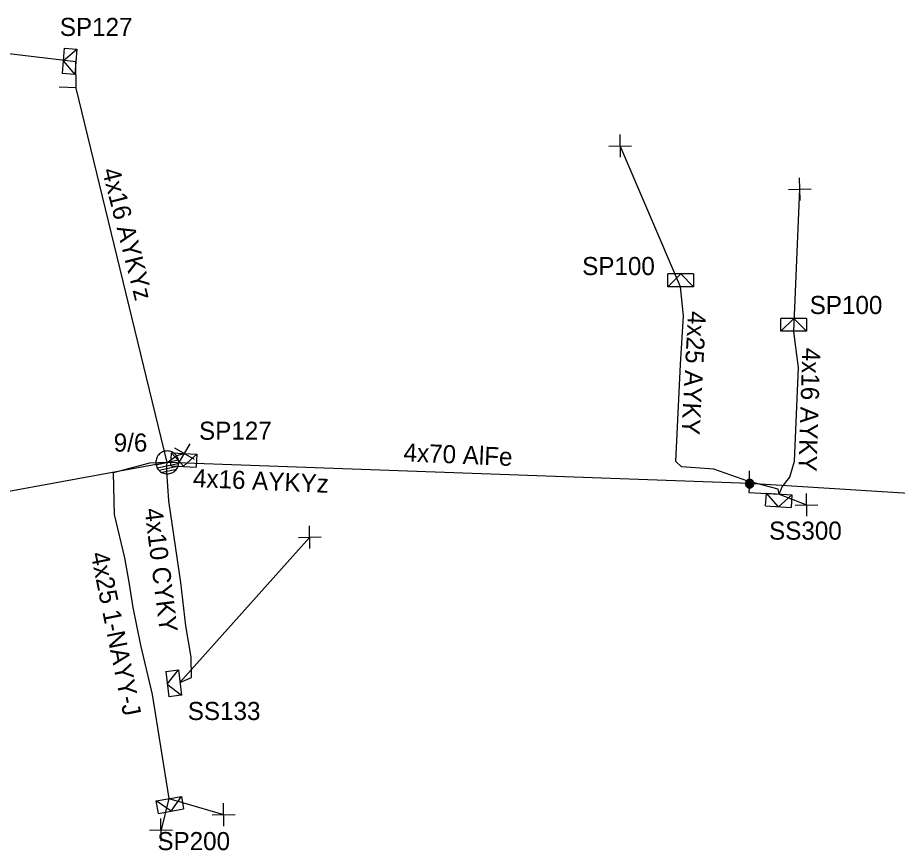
# Model space of a CAD drawing. Extents: x -762504 to -761250, y -1152974 to -1152253.
# Drawn here: x -761535.36 to -761487.02, y -1152548.71 to -1152502.95 of the extents above; entities that cross this region are included whole.
import ezdxf

# ---------------------------------------------------------------- set-up
doc = ezdxf.new("R2010")
doc.units = 0
for name, color, linetype in [('Vrstva 1', 7, 'Continuous'), ('Vrstva 12', 7, 'Continuous'), ('Vrstva 13', 7, 'Continuous'), ('Vrstva 2', 7, 'Continuous'), ('Vrstva 31', 7, 'Continuous'), ('Vrstva 33', 7, 'Continuous'), ('Vrstva 34', 7, 'Continuous'), ('Vrstva 5', 7, 'Continuous'), ('Vrstva 52', 7, 'Continuous'), ('Vrstva 54', 7, 'Continuous'), ('Vrstva 55', 7, 'Continuous'), ('Vrstva 59', 7, 'Continuous')]:
    doc.layers.add(name, color=color, linetype=linetype)

msp = doc.modelspace()

# ---------------------------------------------------------------- linework, layer by layer
at = {"layer": 'Vrstva 1'}
for points in [[(-761495.14, -1152528.56), (-761527.14, -1152527.39), (-761557.16, -1152532.89)], [(-761457.83, -1152530.5), (-761470.65, -1152530.09), (-761495.14, -1152528.56)]]:
    msp.add_lwpolyline(points, dxfattribs=at)
at = {"layer": 'Vrstva 13'}
for points in [[(-761532.142, -1152506.819), (-761533.078, -1152506.77)], [(-761526.523, -1152527.263), (-761526.54, -1152527.199), (-761526.563, -1152527.138), (-761526.593, -1152527.079), (-761526.629, -1152527.023), (-761526.67, -1152526.972), (-761526.717, -1152526.926), (-761526.768, -1152526.884), (-761526.823, -1152526.848), (-761526.882, -1152526.818), (-761526.944, -1152526.794), (-761527.008, -1152526.777), (-761527.073, -1152526.767), (-761527.139, -1152526.764), (-761527.204, -1152526.767), (-761527.27, -1152526.778), (-761527.333, -1152526.794), (-761527.395, -1152526.818), (-761527.454, -1152526.848), (-761527.509, -1152526.884), (-761527.56, -1152526.925), (-761527.607, -1152526.972), (-761527.648, -1152527.023), (-761527.684, -1152527.079), (-761527.714, -1152527.138), (-761527.738, -1152527.199), (-761527.755, -1152527.263), (-761527.765, -1152527.328), (-761527.769, -1152527.394), (-761527.765, -1152527.459), (-761527.755, -1152527.525), (-761527.738, -1152527.588), (-761527.714, -1152527.65), (-761527.684, -1152527.709), (-761527.648, -1152527.764), (-761527.607, -1152527.815), (-761527.56, -1152527.862), (-761527.509, -1152527.903), (-761527.454, -1152527.939), (-761527.395, -1152527.969), (-761527.333, -1152527.993), (-761527.269, -1152528.01), (-761527.205, -1152528.02), (-761527.139, -1152528.024), (-761527.073, -1152528.02), (-761527.008, -1152528.01), (-761526.944, -1152527.993), (-761526.882, -1152527.969), (-761526.824, -1152527.939), (-761526.768, -1152527.903), (-761526.717, -1152527.862), (-761526.67, -1152527.815), (-761526.629, -1152527.764), (-761526.593, -1152527.709), (-761526.563, -1152527.65), (-761526.539, -1152527.588), (-761526.522, -1152527.525), (-761526.512, -1152527.46), (-761526.509, -1152527.394), (-761526.512, -1152527.328), (-761526.523, -1152527.263)], [(-761527.757, -1152527.521), (-761526.525, -1152527.259)], [(-761527.692, -1152527.688), (-761526.546, -1152527.445)], [(-761527.574, -1152527.814), (-761526.583, -1152527.603)], [(-761527.409, -1152527.93), (-761526.696, -1152527.779)], [(-761495.14, -1152528.326), (-761495.14, -1152527.856)], [(-761494.905, -1152528.561), (-761494.906, -1152528.537), (-761494.91, -1152528.512), (-761494.916, -1152528.489), (-761494.925, -1152528.466), (-761494.936, -1152528.444), (-761494.949, -1152528.423), (-761494.965, -1152528.404), (-761494.982, -1152528.387), (-761495.001, -1152528.371), (-761495.022, -1152528.358), (-761495.044, -1152528.347), (-761495.067, -1152528.338), (-761495.091, -1152528.331), (-761495.115, -1152528.327), (-761495.14, -1152528.326), (-761495.164, -1152528.327), (-761495.188, -1152528.331), (-761495.212, -1152528.338), (-761495.235, -1152528.347), (-761495.257, -1152528.358), (-761495.278, -1152528.371), (-761495.297, -1152528.387), (-761495.314, -1152528.404), (-761495.33, -1152528.423), (-761495.343, -1152528.444), (-761495.354, -1152528.466), (-761495.363, -1152528.489), (-761495.369, -1152528.512), (-761495.373, -1152528.537), (-761495.375, -1152528.561), (-761495.373, -1152528.586), (-761495.369, -1152528.61), (-761495.363, -1152528.634), (-761495.354, -1152528.657), (-761495.343, -1152528.679), (-761495.33, -1152528.699), (-761495.314, -1152528.718), (-761495.297, -1152528.736), (-761495.278, -1152528.751), (-761495.257, -1152528.765), (-761495.235, -1152528.776), (-761495.212, -1152528.785), (-761495.188, -1152528.791), (-761495.164, -1152528.795), (-761495.14, -1152528.796), (-761495.115, -1152528.795), (-761495.091, -1152528.791), (-761495.067, -1152528.785), (-761495.044, -1152528.776), (-761495.022, -1152528.765), (-761495.001, -1152528.751), (-761494.982, -1152528.736), (-761494.965, -1152528.718), (-761494.949, -1152528.699), (-761494.936, -1152528.679), (-761494.925, -1152528.657), (-761494.916, -1152528.634), (-761494.91, -1152528.61), (-761494.906, -1152528.586), (-761494.905, -1152528.561)], [(-761494.905, -1152528.561), (-761494.906, -1152528.537), (-761494.91, -1152528.512), (-761494.916, -1152528.489), (-761494.925, -1152528.466), (-761494.936, -1152528.444), (-761494.949, -1152528.423), (-761494.965, -1152528.404), (-761494.982, -1152528.387), (-761495.001, -1152528.371), (-761495.022, -1152528.358), (-761495.044, -1152528.347), (-761495.067, -1152528.338), (-761495.091, -1152528.331), (-761495.115, -1152528.327), (-761495.14, -1152528.326), (-761495.164, -1152528.327), (-761495.188, -1152528.331), (-761495.212, -1152528.338), (-761495.235, -1152528.347), (-761495.257, -1152528.358), (-761495.278, -1152528.371), (-761495.297, -1152528.387), (-761495.314, -1152528.404), (-761495.33, -1152528.423), (-761495.343, -1152528.444), (-761495.354, -1152528.466), (-761495.363, -1152528.489), (-761495.369, -1152528.512), (-761495.373, -1152528.537), (-761495.375, -1152528.561), (-761495.373, -1152528.586), (-761495.369, -1152528.61), (-761495.363, -1152528.634), (-761495.354, -1152528.657), (-761495.343, -1152528.679), (-761495.33, -1152528.699), (-761495.314, -1152528.718), (-761495.297, -1152528.736), (-761495.278, -1152528.751), (-761495.257, -1152528.765), (-761495.235, -1152528.776), (-761495.212, -1152528.785), (-761495.188, -1152528.791), (-761495.164, -1152528.795), (-761495.14, -1152528.796), (-761495.115, -1152528.795), (-761495.091, -1152528.791), (-761495.067, -1152528.785), (-761495.044, -1152528.776), (-761495.022, -1152528.765), (-761495.001, -1152528.751), (-761494.982, -1152528.736), (-761494.965, -1152528.718), (-761494.949, -1152528.699), (-761494.936, -1152528.679), (-761494.925, -1152528.657), (-761494.916, -1152528.634), (-761494.91, -1152528.61), (-761494.906, -1152528.586), (-761494.905, -1152528.561)], [(-761494.934, -1152528.561), (-761494.935, -1152528.54), (-761494.939, -1152528.518), (-761494.944, -1152528.498), (-761494.952, -1152528.478), (-761494.962, -1152528.459), (-761494.973, -1152528.44), (-761494.987, -1152528.424), (-761495.002, -1152528.409), (-761495.019, -1152528.395), (-761495.037, -1152528.383), (-761495.056, -1152528.374), (-761495.076, -1152528.366), (-761495.097, -1152528.36), (-761495.118, -1152528.357), (-761495.14, -1152528.356), (-761495.161, -1152528.357), (-761495.182, -1152528.36), (-761495.203, -1152528.366), (-761495.223, -1152528.374), (-761495.242, -1152528.383), (-761495.26, -1152528.395), (-761495.277, -1152528.409), (-761495.292, -1152528.424), (-761495.306, -1152528.44), (-761495.317, -1152528.459), (-761495.327, -1152528.478), (-761495.335, -1152528.498), (-761495.34, -1152528.518), (-761495.344, -1152528.54), (-761495.345, -1152528.561), (-761495.344, -1152528.583), (-761495.34, -1152528.604), (-761495.335, -1152528.625), (-761495.327, -1152528.645), (-761495.317, -1152528.664), (-761495.306, -1152528.682), (-761495.292, -1152528.699), (-761495.277, -1152528.714), (-761495.26, -1152528.727), (-761495.242, -1152528.739), (-761495.223, -1152528.749), (-761495.203, -1152528.757), (-761495.182, -1152528.762), (-761495.161, -1152528.765), (-761495.14, -1152528.767), (-761495.118, -1152528.765), (-761495.097, -1152528.762), (-761495.076, -1152528.757), (-761495.056, -1152528.749), (-761495.037, -1152528.739), (-761495.019, -1152528.727), (-761495.002, -1152528.714), (-761494.987, -1152528.699), (-761494.973, -1152528.682), (-761494.962, -1152528.664), (-761494.952, -1152528.645), (-761494.944, -1152528.625), (-761494.939, -1152528.604), (-761494.935, -1152528.583), (-761494.934, -1152528.561)], [(-761494.964, -1152528.561), (-761494.965, -1152528.543), (-761494.968, -1152528.525), (-761494.972, -1152528.507), (-761494.979, -1152528.49), (-761494.987, -1152528.473), (-761494.997, -1152528.458), (-761495.009, -1152528.444), (-761495.022, -1152528.431), (-761495.036, -1152528.419), (-761495.052, -1152528.409), (-761495.068, -1152528.401), (-761495.085, -1152528.394), (-761495.103, -1152528.389), (-761495.121, -1152528.386), (-761495.14, -1152528.385), (-761495.158, -1152528.386), (-761495.176, -1152528.389), (-761495.194, -1152528.394), (-761495.211, -1152528.401), (-761495.227, -1152528.409), (-761495.243, -1152528.419), (-761495.257, -1152528.431), (-761495.27, -1152528.444), (-761495.282, -1152528.458), (-761495.292, -1152528.473), (-761495.3, -1152528.49), (-761495.307, -1152528.507), (-761495.312, -1152528.525), (-761495.314, -1152528.543), (-761495.315, -1152528.561), (-761495.314, -1152528.58), (-761495.312, -1152528.598), (-761495.307, -1152528.616), (-761495.3, -1152528.633), (-761495.292, -1152528.649), (-761495.282, -1152528.665), (-761495.27, -1152528.679), (-761495.257, -1152528.692), (-761495.243, -1152528.703), (-761495.227, -1152528.713), (-761495.211, -1152528.722), (-761495.194, -1152528.728), (-761495.176, -1152528.733), (-761495.158, -1152528.736), (-761495.14, -1152528.737), (-761495.121, -1152528.736), (-761495.103, -1152528.733), (-761495.085, -1152528.728), (-761495.068, -1152528.722), (-761495.052, -1152528.713), (-761495.036, -1152528.703), (-761495.022, -1152528.692), (-761495.009, -1152528.679), (-761494.997, -1152528.665), (-761494.987, -1152528.649), (-761494.979, -1152528.633), (-761494.972, -1152528.616), (-761494.968, -1152528.598), (-761494.965, -1152528.58), (-761494.964, -1152528.561)], [(-761494.993, -1152528.561), (-761494.994, -1152528.546), (-761494.997, -1152528.531), (-761495.001, -1152528.516), (-761495.006, -1152528.502), (-761495.013, -1152528.488), (-761495.021, -1152528.475), (-761495.031, -1152528.463), (-761495.042, -1152528.453), (-761495.054, -1152528.443), (-761495.067, -1152528.435), (-761495.08, -1152528.428), (-761495.094, -1152528.422), (-761495.109, -1152528.418), (-761495.124, -1152528.416), (-761495.14, -1152528.415), (-761495.155, -1152528.416), (-761495.17, -1152528.418), (-761495.185, -1152528.422), (-761495.199, -1152528.428), (-761495.213, -1152528.435), (-761495.226, -1152528.443), (-761495.237, -1152528.453), (-761495.248, -1152528.463), (-761495.258, -1152528.475), (-761495.266, -1152528.488), (-761495.273, -1152528.502), (-761495.279, -1152528.516), (-761495.283, -1152528.531), (-761495.285, -1152528.546), (-761495.286, -1152528.561), (-761495.285, -1152528.576), (-761495.283, -1152528.592), (-761495.279, -1152528.606), (-761495.273, -1152528.621), (-761495.266, -1152528.634), (-761495.258, -1152528.647), (-761495.248, -1152528.659), (-761495.237, -1152528.67), (-761495.226, -1152528.679), (-761495.213, -1152528.688), (-761495.199, -1152528.695), (-761495.185, -1152528.7), (-761495.17, -1152528.704), (-761495.155, -1152528.707), (-761495.14, -1152528.707), (-761495.124, -1152528.707), (-761495.109, -1152528.704), (-761495.094, -1152528.7), (-761495.08, -1152528.695), (-761495.067, -1152528.688), (-761495.054, -1152528.679), (-761495.042, -1152528.67), (-761495.031, -1152528.659), (-761495.021, -1152528.647), (-761495.013, -1152528.634), (-761495.006, -1152528.621), (-761495.001, -1152528.606), (-761494.997, -1152528.592), (-761494.994, -1152528.576), (-761494.993, -1152528.561)], [(-761495.023, -1152528.561), (-761495.024, -1152528.549), (-761495.026, -1152528.537), (-761495.029, -1152528.525), (-761495.033, -1152528.514), (-761495.039, -1152528.503), (-761495.045, -1152528.493), (-761495.053, -1152528.483), (-761495.062, -1152528.475), (-761495.071, -1152528.467), (-761495.081, -1152528.46), (-761495.092, -1152528.455), (-761495.104, -1152528.45), (-761495.115, -1152528.447), (-761495.127, -1152528.445), (-761495.14, -1152528.445), (-761495.152, -1152528.445), (-761495.164, -1152528.447), (-761495.176, -1152528.45), (-761495.187, -1152528.455), (-761495.198, -1152528.46), (-761495.208, -1152528.467), (-761495.218, -1152528.475), (-761495.226, -1152528.483), (-761495.234, -1152528.493), (-761495.241, -1152528.503), (-761495.246, -1152528.514), (-761495.25, -1152528.525), (-761495.254, -1152528.537), (-761495.256, -1152528.549), (-761495.256, -1152528.561), (-761495.256, -1152528.573), (-761495.254, -1152528.585), (-761495.25, -1152528.597), (-761495.246, -1152528.609), (-761495.241, -1152528.619), (-761495.234, -1152528.63), (-761495.226, -1152528.639), (-761495.218, -1152528.648), (-761495.208, -1152528.655), (-761495.198, -1152528.662), (-761495.187, -1152528.668), (-761495.176, -1152528.672), (-761495.164, -1152528.675), (-761495.152, -1152528.677), (-761495.14, -1152528.678), (-761495.127, -1152528.677), (-761495.115, -1152528.675), (-761495.104, -1152528.672), (-761495.092, -1152528.668), (-761495.081, -1152528.662), (-761495.071, -1152528.655), (-761495.062, -1152528.648), (-761495.053, -1152528.639), (-761495.045, -1152528.63), (-761495.039, -1152528.619), (-761495.033, -1152528.609), (-761495.029, -1152528.597), (-761495.026, -1152528.585), (-761495.024, -1152528.573), (-761495.023, -1152528.561)], [(-761495.053, -1152528.561), (-761495.053, -1152528.552), (-761495.055, -1152528.543), (-761495.057, -1152528.534), (-761495.06, -1152528.526), (-761495.064, -1152528.518), (-761495.069, -1152528.51), (-761495.075, -1152528.503), (-761495.081, -1152528.497), (-761495.089, -1152528.491), (-761495.096, -1152528.486), (-761495.104, -1152528.482), (-761495.113, -1152528.478), (-761495.121, -1152528.476), (-761495.131, -1152528.475), (-761495.14, -1152528.474), (-761495.149, -1152528.475), (-761495.158, -1152528.476), (-761495.166, -1152528.478), (-761495.175, -1152528.482), (-761495.183, -1152528.486), (-761495.191, -1152528.491), (-761495.198, -1152528.497), (-761495.204, -1152528.503), (-761495.21, -1152528.51), (-761495.215, -1152528.518), (-761495.219, -1152528.526), (-761495.222, -1152528.534), (-761495.225, -1152528.543), (-761495.226, -1152528.552), (-761495.227, -1152528.561), (-761495.226, -1152528.57), (-761495.225, -1152528.579), (-761495.222, -1152528.588), (-761495.219, -1152528.597), (-761495.215, -1152528.605), (-761495.21, -1152528.612), (-761495.204, -1152528.619), (-761495.198, -1152528.626), (-761495.191, -1152528.632), (-761495.183, -1152528.637), (-761495.175, -1152528.641), (-761495.166, -1152528.644), (-761495.158, -1152528.646), (-761495.149, -1152528.648), (-761495.14, -1152528.648), (-761495.131, -1152528.648), (-761495.121, -1152528.646), (-761495.113, -1152528.644), (-761495.104, -1152528.641), (-761495.096, -1152528.637), (-761495.088, -1152528.632), (-761495.081, -1152528.626), (-761495.075, -1152528.619), (-761495.069, -1152528.612), (-761495.064, -1152528.605), (-761495.06, -1152528.597), (-761495.057, -1152528.588), (-761495.055, -1152528.579), (-761495.053, -1152528.57), (-761495.053, -1152528.561)], [(-761495.082, -1152528.561), (-761495.083, -1152528.555), (-761495.084, -1152528.549), (-761495.085, -1152528.544), (-761495.087, -1152528.538), (-761495.09, -1152528.533), (-761495.093, -1152528.527), (-761495.097, -1152528.523), (-761495.101, -1152528.519), (-761495.106, -1152528.515), (-761495.111, -1152528.512), (-761495.116, -1152528.509), (-761495.122, -1152528.507), (-761495.128, -1152528.505), (-761495.134, -1152528.504), (-761495.14, -1152528.504), (-761495.146, -1152528.504), (-761495.152, -1152528.505), (-761495.157, -1152528.507), (-761495.163, -1152528.509), (-761495.168, -1152528.512), (-761495.173, -1152528.515), (-761495.178, -1152528.519), (-761495.182, -1152528.523), (-761495.186, -1152528.527), (-761495.189, -1152528.533), (-761495.192, -1152528.538), (-761495.194, -1152528.544), (-761495.196, -1152528.549), (-761495.197, -1152528.555), (-761495.197, -1152528.561), (-761495.197, -1152528.567), (-761495.196, -1152528.573), (-761495.194, -1152528.579), (-761495.192, -1152528.585), (-761495.189, -1152528.59), (-761495.186, -1152528.595), (-761495.182, -1152528.6), (-761495.178, -1152528.604), (-761495.173, -1152528.608), (-761495.168, -1152528.611), (-761495.163, -1152528.614), (-761495.157, -1152528.616), (-761495.152, -1152528.617), (-761495.146, -1152528.618), (-761495.14, -1152528.619), (-761495.134, -1152528.618), (-761495.128, -1152528.617), (-761495.122, -1152528.616), (-761495.116, -1152528.614), (-761495.111, -1152528.611), (-761495.106, -1152528.608), (-761495.101, -1152528.604), (-761495.097, -1152528.6), (-761495.093, -1152528.595), (-761495.09, -1152528.59), (-761495.087, -1152528.585), (-761495.085, -1152528.579), (-761495.084, -1152528.573), (-761495.083, -1152528.567), (-761495.082, -1152528.561)], [(-761495.112, -1152528.561), (-761495.112, -1152528.558), (-761495.112, -1152528.555), (-761495.113, -1152528.553), (-761495.114, -1152528.55), (-761495.116, -1152528.547), (-761495.117, -1152528.545), (-761495.119, -1152528.543), (-761495.121, -1152528.541), (-761495.123, -1152528.539), (-761495.126, -1152528.537), (-761495.128, -1152528.536), (-761495.131, -1152528.535), (-761495.134, -1152528.534), (-761495.137, -1152528.534), (-761495.14, -1152528.533), (-761495.142, -1152528.534), (-761495.145, -1152528.534), (-761495.148, -1152528.535), (-761495.151, -1152528.536), (-761495.153, -1152528.537), (-761495.156, -1152528.539), (-761495.158, -1152528.541), (-761495.16, -1152528.543), (-761495.162, -1152528.545), (-761495.164, -1152528.547), (-761495.165, -1152528.55), (-761495.166, -1152528.553), (-761495.167, -1152528.555), (-761495.167, -1152528.558), (-761495.167, -1152528.561), (-761495.167, -1152528.564), (-761495.167, -1152528.567), (-761495.166, -1152528.57), (-761495.165, -1152528.572), (-761495.164, -1152528.575), (-761495.162, -1152528.578), (-761495.16, -1152528.58), (-761495.158, -1152528.582), (-761495.156, -1152528.584), (-761495.153, -1152528.585), (-761495.151, -1152528.587), (-761495.148, -1152528.588), (-761495.145, -1152528.588), (-761495.142, -1152528.589), (-761495.14, -1152528.589), (-761495.137, -1152528.589), (-761495.134, -1152528.588), (-761495.131, -1152528.588), (-761495.128, -1152528.587), (-761495.126, -1152528.585), (-761495.123, -1152528.584), (-761495.121, -1152528.582), (-761495.119, -1152528.58), (-761495.117, -1152528.578), (-761495.116, -1152528.575), (-761495.114, -1152528.572), (-761495.113, -1152528.57), (-761495.112, -1152528.567), (-761495.112, -1152528.564), (-761495.112, -1152528.561)]]:
    msp.add_lwpolyline(points, dxfattribs=at)
at = {"layer": 'Vrstva 31'}
for points in [[(-761532.81, -1152504.63), (-761532.907, -1152506.027)], [(-761532.81, -1152504.63), (-761532.111, -1152504.679), (-761532.209, -1152506.075), (-761532.907, -1152506.027)], [(-761532.858, -1152505.328), (-761532.111, -1152504.679)], [(-761532.858, -1152505.328), (-761532.209, -1152506.075)], [(-761498.227, -1152517.04), (-761499.627, -1152517.04)], [(-761498.927, -1152517.04), (-761499.627, -1152517.74)], [(-761498.227, -1152517.04), (-761498.227, -1152517.74), (-761499.627, -1152517.74), (-761499.627, -1152517.04)], [(-761498.927, -1152517.04), (-761498.227, -1152517.74)], [(-761492.017, -1152519.49), (-761493.417, -1152519.49)], [(-761492.717, -1152519.49), (-761493.417, -1152520.19)], [(-761492.017, -1152519.49), (-761492.017, -1152520.19), (-761493.417, -1152520.19), (-761493.417, -1152519.49)], [(-761492.717, -1152519.49), (-761492.017, -1152520.19)], [(-761526.939, -1152527.573), (-761526.902, -1152526.874), (-761525.504, -1152526.947), (-761525.541, -1152527.646)], [(-761526.24, -1152527.609), (-761526.902, -1152526.874)], [(-761526.24, -1152527.609), (-761525.504, -1152526.947)], [(-761526.939, -1152527.573), (-761525.541, -1152527.646)], [(-761494.26, -1152529.78), (-761494.211, -1152529.081), (-761492.815, -1152529.179), (-761492.863, -1152529.877)], [(-761493.562, -1152529.828), (-761494.211, -1152529.081)], [(-761493.562, -1152529.828), (-761492.815, -1152529.179)], [(-761494.26, -1152529.78), (-761492.863, -1152529.877)], [(-761527.221, -1152538.878), (-761526.526, -1152538.792), (-761526.355, -1152540.182), (-761527.05, -1152540.267)], [(-761527.221, -1152538.878), (-761527.05, -1152540.267)], [(-761527.135, -1152539.572), (-761526.526, -1152538.792)], [(-761527.135, -1152539.572), (-761526.355, -1152540.182)], [(-761527.621, -1152546.681), (-761527.742, -1152545.992), (-761526.364, -1152545.749), (-761526.242, -1152546.438)], [(-761526.931, -1152546.56), (-761526.364, -1152545.749)], [(-761526.931, -1152546.56), (-761527.742, -1152545.992)], [(-761527.621, -1152546.681), (-761526.242, -1152546.438)]]:
    msp.add_lwpolyline(points, dxfattribs=at)
at = {"layer": 'Vrstva 34'}
for points in [[(-761502.239, -1152510.625), (-761502.261, -1152509.375)], [(-761502.875, -1152510.011), (-761501.625, -1152509.989)], [(-761492.369, -1152513.005), (-761492.391, -1152511.755)], [(-761493.005, -1152512.391), (-761491.755, -1152512.369)], [(-761526.741, -1152526.597), (-761525.659, -1152527.222)], [(-761526.513, -1152527.451), (-761525.888, -1152526.369)], [(-761491.999, -1152530.355), (-761492.021, -1152529.105)], [(-761492.635, -1152529.741), (-761491.385, -1152529.719)], [(-761519.299, -1152532.125), (-761519.321, -1152530.875)], [(-761519.935, -1152531.511), (-761518.685, -1152531.489)], [(-761524.029, -1152547.375), (-761524.051, -1152546.125)], [(-761524.665, -1152546.761), (-761523.415, -1152546.739)], [(-761527.469, -1152548.215), (-761527.491, -1152546.965)], [(-761528.105, -1152547.601), (-761526.855, -1152547.579)]]:
    msp.add_lwpolyline(points, dxfattribs=at)
at = {"layer": 'Vrstva 5'}
msp.add_lwpolyline([(-761495.14, -1152528.56), (-761495.18, -1152529.05), (-761493.51, -1152529.13)], dxfattribs=at)
at = {"layer": 'Vrstva 52'}
for points in [[(-761493.51, -1152529.13), (-761493.58, -1152528.86), (-761495.23, -1152528.43), (-761497.1, -1152527.77), (-761498.88, -1152527.64), (-761499.2, -1152527.35), (-761498.94, -1152522.02), (-761498.78, -1152519.34), (-761498.93, -1152517.74)], [(-761493.51, -1152529.13), (-761493.36, -1152528.73), (-761492.93, -1152528.2), (-761492.67, -1152527.33), (-761492.46, -1152522.18), (-761492.64, -1152520.79), (-761492.72, -1152520.19)], [(-761527.14, -1152527.39), (-761528.12, -1152527.43), (-761530.11, -1152527.96), (-761530.05, -1152530.25), (-761529.49, -1152532.64), (-761529.25, -1152533.98), (-761529.03, -1152535.36), (-761528.61, -1152537.44), (-761527.97, -1152540.15), (-761527.05, -1152545.87)], [(-761526.44, -1152539.49), (-761525.81, -1152539.22), (-761525.83, -1152538.09), (-761526.11, -1152536.38), (-761526.4, -1152533.99), (-761527.06, -1152529.51), (-761527.17, -1152527.9), (-761527.17, -1152527.58), (-761527.14, -1152527.39)]]:
    msp.add_lwpolyline(points, dxfattribs=at)
at = {"layer": 'Vrstva 54'}
for points in [[(-761527.14, -1152527.39), (-761532.14, -1152506.82), (-761532.16, -1152505.38)], [(-761527.14, -1152527.39), (-761526.62, -1152527.02), (-761526.2, -1152526.91)]]:
    msp.add_lwpolyline(points, dxfattribs=at)
at = {"layer": 'Vrstva 59'}
for points in [[(-761532.16, -1152505.38), (-761543.69, -1152504)], [(-761498.93, -1152517.74), (-761502.25, -1152510)], [(-761492.72, -1152520.19), (-761492.38, -1152512.38)], [(-761493.51, -1152529.13), (-761492.01, -1152529.73)], [(-761526.44, -1152539.49), (-761519.31, -1152531.5)], [(-761527.05, -1152545.87), (-761527.48, -1152547.59)], [(-761527.05, -1152545.87), (-761524.04, -1152546.75)]]:
    msp.add_lwpolyline(points, dxfattribs=at)

# ---------------------------------------------------------------- texts
at = {"layer": 'Vrstva 12'}
msp.add_text('9/6', height=0.9943, dxfattribs=at).set_placement((-761530.08, -1152526.8))
at = {"layer": 'Vrstva 2'}
msp.add_text('4x70 AlFe', height=0.9943, rotation=357.5027, dxfattribs=at).set_placement((-761514.17, -1152527.33))
at = {"layer": 'Vrstva 33'}
for s, p in [('SP127', (-761533.04, -1152503.96)), ('SP100', (-761504.34, -1152517.1)), ('SP100', (-761491.84, -1152519.24)), ('SP127', (-761525.39, -1152526.15)), ('SS300', (-761494.07, -1152531.64)), ('SS133', (-761526.01, -1152541.55)), ('SP200', (-761527.68, -1152548.7))]:
    msp.add_text(s, height=0.9943, dxfattribs=at).set_placement(p)
at = {"layer": 'Vrstva 54'}
for s, height, rotation, p in [('4x25 AYKY', 0.9943, 266.936, (-761498.52, -1152519.06)), ('4x16 AYKY', 0.9943, 268.1705, (-761492.24, -1152521.08)), ('4x10 CYKY', 0.9943, 277.0667, (-761528.39, -1152529.96)), ('4x25 1-NAYY-J', 0.99429, 281.4158, (-761531.35, -1152532.41))]:
    msp.add_text(s, height=height, rotation=rotation, dxfattribs=at).set_placement(p)
at = {"layer": 'Vrstva 55'}
for rotation, p in [(284.293, (-761530.73, -1152511.34)), (357.495, (-761525.74, -1152528.74))]:
    msp.add_text('4x16 AYKYz', height=0.9943, rotation=rotation, dxfattribs=at).set_placement(p)

doc.saveas('drawing.dxf')
